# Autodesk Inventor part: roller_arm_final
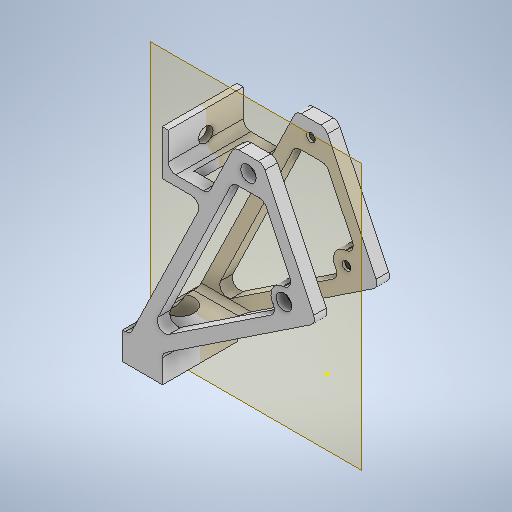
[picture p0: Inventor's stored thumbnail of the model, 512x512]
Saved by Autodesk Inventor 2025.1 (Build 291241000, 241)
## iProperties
Created: 2024-11
Part Number: roller_arm_final
Material: Generic
Document SubType Name: Modeling
Designer: mansa
Density: 1 g/cm^3
Appearance: Default
Author: mansa
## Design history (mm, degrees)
sketch "Sketch1"
  geometry: 1 further point
feature "Surface1"
workplane "Work Plane1"
sketch "Sketch2"
  geometry: L1 (16, 0)-(0, 0) reference; L2 (16, 0)-(16, 11) reference; L3 (16, 11)-(0, 11) reference; L4 (0, 0)-(0, 11) reference; 1 further point
extrude "Extrusion1" new body sketch "Sketch2" stored distance "d0" = 20; taper "d1" = 0 deg
sketch "Sketch6"
  geometry: L1 (16, 0)-(6, 0); L2 (6, 0)-(6, -20); L3 (6, -20)-(16, -20); L4 (16, -20)-(16, 0); L5 (16, 0)-(16, -20) reference; L6 (0, 0)-(16, 0) reference; 2 further points
  constraints: 8 end point, 2 parallel, 1 horizontal, 1 midpoint, 1 perpendicular
  dimensions: "d7" = 20 distance between parallel lines of L3 L1; "d8" = 10 distance of L1.start L1.end; "d10" = 0 distance between parallel lines of L5 L4; "d11" = 0 distance from line of point (8, 0) L1
sketch "Sketch8"
  geometry: L1 (56, 44.1)-(46, 44.1); L2 (46, 44.1)-(46, 24.1); L3 (46, 24.1)-(56, 24.1); L4 (56, 24.1)-(56, 44.1); L5 (16.187, 44.1)-(6.187, 44.1) reference; L6 (6.187, 24.1)-(16.187, 24.1) reference; 3 further points; 1 other entity
  constraints: 8 end point, 2 parallel, 1 collinear, 1 horizontal, 1 perpendicular, 1 other
  dimensions: "d13" = 10 distance between parallel lines of L2 L4; "d14" = 20 distance of L3.end L1.start; "d15" = 30 dimension on L2
loft "Loft1" sketch "Sketch6", "Sketch8" dims "d16" = 0, "d17" = 90 deg, "d18" = 0, "d19" = 90 deg
sketch "Sketch9"
  geometry: L1 (48.4, 69.2)-(116.6, 69.2) reference; L2 (72.5, 69.2)-(92.5, 69.2); L3 (92.5, 69.2)-(92.5, 87.2); L4 (92.5, 87.2)-(72.5, 87.2); L5 (72.5, 87.2)-(72.5, 69.2); L6 (48.4, 91)-(116.6, 91) reference; L7 (82.5, 91)-(82.5, 65.399); 1 further point
  constraints: 10 end point, 2 parallel, 2 perpendicular, 1 horizontal, 1 midpoint, 1 point on line, 1 other
  dimensions: "d20" = 18 distance of L4.end L2.start; "d21" = 20 distance of L3.end L4.end
extrude "Extrusion2" join sketch "Sketch9" distance "d22" = 2.5; taper "d23" = 0 deg
sketch "Sketch10"
  geometry: L1 (72.5, 87.2)-(72.5, 69.2) reference; L2 (72.5, 69.2)-(92.5, 69.2) reference; L3 (72.5, 73.2)-(92.5, 73.2); L4 (92.5, 73.2)-(92.5, 69.2); L5 (92.5, 69.2)-(72.5, 69.2); L6 (72.5, 69.2)-(72.5, 73.2); 1 further point
  constraints: 8 end point, 2 parallel, 1 horizontal, 1 perpendicular, 1 point on line
  dimensions: "d24" = 4 distance of L3.end L2.end
extrude "Extrusion3" join sketch "Sketch10" stored distance "d25" = 2.5; taper "d26" = 0 deg
feature "Surface2"
feature "Surface3"
sketch "Sketch13"
  geometry: L1 (39.813, 84.757)-(0, 11) reference; L2 (39.813, 84.757)-(55.958, 51.122); L3 (55.958, 51.122)-(0, 11); 1 further point
  constraints: 4 end point
  dimensions: "d33" = 26 deg angle of L3 L1; "d34" = 54 deg angle of L1 L2
extrude "Extrusion5" join sketch "Sketch13" stored distance "d35" = 20; taper "d36" = 0 deg
fillet "Fillet2" dims "d37" = 3
sketch "Sketch14"
  geometry: C1 r 2.75 at (34.813, 78.792) reference; C2 r 2.75 at (48.6, 53.017) reference; C3 r 1.75 at (34.813, 78.792); C4 r 1.75 at (48.6, 53.017); 1 further point
  constraints: 2 centre point, 2 coincident
  dimensions: "d39" = 3.5 diameter of C3; "d40" = 3.5 diameter of C4 (= d39)
extrude "Extrusion6" cut sketch "Sketch14" extent not by distance; stored distance "d41" = 10; taper "d42" = 0 deg
workplane "Work Plane5"
sketch "Sketch15"
  geometry: L1 (92.5, 87.2)-(72.5, 87.2) reference; L2 (72.5, 51.234)-(72.5, 80.898) reference; L3 (92.5, 51.234)-(92.5, 80.898) reference; L4 (72.5, 9.74)-(72.5, 47.498) reference; L5 (92.5, 9.74)-(92.5, 47.498) reference; L6 (92.5, 9.74)-(72.5, 9.74) reference; L7 (72.5, 87.2)-(72.5, 76.2) reference; L8 (92.5, 76.2)-(92.5, 87.2) reference; L9 (77.5, 85.2)-(87.5, 85.2); L10 (87.5, 85.2)-(87.5, 12.2); L11 (87.5, 12.2)-(77.5, 12.2); L12 (77.5, 12.2)-(77.5, 85.2); 2 further points
  constraints: 8 end point, 2 parallel, 1 horizontal, 1 midpoint, 1 perpendicular
  dimensions: "d45" = 5 distance between parallel lines of L2 L12; "d46" = 5 distance between parallel lines of L3 L10; "d48" = 73 distance between parallel lines of L11 L9; "d49" = 2 distance from line of point (82.5, 85.2) L1
extrude "Extrusion7" cut sketch "Sketch15" distance "d50" = 63.75; taper "d51" = 0 deg
sketch "Sketch16"
  geometry: L1 (77.5, 39.064)-(87.5, 39.064) reference; L2 (77.5, 13.369)-(77.5, 39.064) reference; L3 (87.5, 13.369)-(77.5, 13.369) reference; L4 (87.5, 39.064)-(87.5, 13.369) reference; 1 further point
extrude "Extrusion8" cut sketch "Sketch16" distance "d52" = 34; taper "d53" = 0 deg
sketch "Sketch17"
  geometry: L1 (-1.252, 11.898)-(-53.912, 49.655); L2 (-20.191, 66.932)-(9.15, 12.575); L3 (-28.963, 83.182)-(-25.589, 76.932); L4 (-37.925, 84.757)-(-31.603, 84.757); L5 (-54.868, 53.391)-(-40.63, 83.055); L6 (-32.433, 72.4)-(-43.132, 50.112); L7 (-42.494, 47.621)-(-5.414, 21.034); L8 (-2.488, 23.609)-(-28.87, 72.485); A1 r 3 centre (-52.164, 52.093) between (-54.868, 53.391) and (-53.912, 49.655); A2 r 3 centre (-31.603, 81.757) between (-28.963, 83.182) and (-31.603, 84.757); A3 r 3 centre (-37.925, 81.757) between (-37.925, 84.757) and (-40.63, 83.055); A4 r 2 centre (-4.248, 22.659) between (-5.414, 21.034) and (-2.488, 23.609); A5 r 2 centre (-30.63, 71.535) between (-28.87, 72.485) and (-32.433, 72.4); A6 r 2 centre (-41.329, 49.246) between (-43.132, 50.112) and (-42.494, 47.621); 1 further point
  constraints: 6 centre point, 6 end point, 6 point on circle, 6 tangent, 3 parallel, 2 equal radius
  dimensions: "d54" = 5 distance between parallel lines of L2 L8; "d55" = 5 distance between parallel lines of L1 L7; "d56" = 12 distance between parallel lines of L5 L6; "d57" = 2 radius of A4 (derived)
extrude "Extrusion9" cut sketch "Sketch17" extent not by distance; stored distance "d58" = 0; taper "d59" = 0 deg
sketch "Sketch18"
  geometry: L1 (92.5, 87.2)-(72.5, 87.2) reference; L2 (82.5, 87.2)-(82.5, 73.2); L3 (72.5, 73.2)-(92.5, 73.2) reference; C1 r 2.9 at (82.5, 80.1); 1 further point
  constraints: 2 end point, 2 midpoint, 1 centre point, 1 point on line
  dimensions: "d61" = 7.1 distance from line of C1.centre L1; "d62" = 5.8 diameter of C1
extrude "Hole top" cut sketch "Sketch18" extent not by distance; stored distance "d63" = 0; taper "d64" = 0 deg
workplane "Work Plane6"
sketch "Sketch20"
  geometry: L1 (0, 20)-(0, 0) reference; L2 (16, 20)-(16, 0) reference; L3 (0, 0)-(16, 20); L4 (0, 20)-(16, 0); C1 r 2.9 at (8, 10); 1 further point
  constraints: 4 end point, 1 centre point, 1 midpoint
  dimensions: "d68" = 5.8 diameter of C1
extrude "hole bottom 2" cut sketch "Sketch20" distance "d69" = 4; taper "d70" = 0 deg
sketch "Sketch21"
  geometry: C1 r 5.5 at (0, 0); 1 further point
  constraints: 1 centre point
  dimensions: "d71" = 11 diameter of C1
extrude "Hole bottom" cut sketch "Sketch21" extent not by distance; stored distance "d72" = 0; taper "d73" = 0 deg
workplane "Work Plane7"
split "Split1"
sketch "Sketch22"
  geometry: C1 r 1.75 at (48.787, -18.34) reference; C2 r 1.75 at (35, 7.435) reference; C3 r 3.1 at (35, 7.435); C4 r 3.1 at (48.787, -18.34); 1 further point
  constraints: 2 centre point, 2 coincident
  dimensions: "d78" = 6.2 diameter of C4; "d79" = 6.2 diameter of C3 (= d78)
extrude "Extrusion14" cut sketch "Sketch22" distance "d80" = 4; taper "d81" = 0 deg
node "Direct Edit2"
sketch "Sketch23"
  geometry: L1 (-37.382, 8.81)-(-36.588, 10.185) reference; L2 (-38.175, 7.435)-(-37.382, 8.81) reference; L3 (-37.382, 6.06)-(-38.175, 7.435) reference; L4 (-36.588, 4.685)-(-37.382, 6.06) reference; L5 (-35, 4.685)-(-36.588, 4.685) reference; L6 (-33.412, 4.685)-(-35, 4.685) reference; L7 (-33.412, 4.685)-(-32.618, 6.06) reference; L8 (-32.618, 6.06)-(-31.825, 7.435) reference; L9 (-31.825, 7.435)-(-32.618, 8.81) reference; L10 (-32.618, 8.81)-(-33.412, 10.185) reference; L11 (-33.412, 10.185)-(-35, 10.185) reference; L12 (-35, 10.185)-(-36.588, 10.185) reference; L13 (-36.876, 10.685)-(-37.815, 9.06); L14 (-37.815, 9.06)-(-38.753, 7.435); L15 (-38.753, 7.435)-(-37.815, 5.81); L16 (-37.815, 5.81)-(-36.876, 4.185); L17 (-36.876, 4.185)-(-35, 4.185); L18 (-35, 4.185)-(-33.124, 4.185); L19 (-33.124, 4.185)-(-32.185, 5.81); L20 (-32.185, 5.81)-(-31.247, 7.435); L21 (-31.247, 7.435)-(-32.185, 9.06); L22 (-32.185, 9.06)-(-33.124, 10.685); L23 (-33.124, 10.685)-(-35, 10.685); L24 (-35, 10.685)-(-36.876, 10.685); L25 (-50.375, -15.59)-(-51.168, -16.965) reference; L26 (-51.168, -16.965)-(-51.962, -18.34) reference; L27 (-48.787, -15.59)-(-50.375, -15.59) reference; L28 (-47.199, -15.59)-(-48.787, -15.59) reference; L29 (-46.405, -16.965)-(-47.199, -15.59) reference; L30 (-45.611, -18.34)-(-46.405, -16.965) reference; L31 (-46.405, -19.715)-(-45.611, -18.34) reference; L32 (-47.199, -21.09)-(-46.405, -19.715) reference; L33 (-48.787, -21.09)-(-47.199, -21.09) reference; L34 (-50.375, -21.09)-(-48.787, -21.09) reference; L35 (-51.168, -19.715)-(-50.375, -21.09) reference; L36 (-51.962, -18.34)-(-51.168, -19.715) reference; L37 (-46.91, -15.09)-(-48.787, -15.09); L38 (-48.787, -15.09)-(-50.663, -15.09); L39 (-50.663, -15.09)-(-51.601, -16.715); L40 (-51.601, -16.715)-(-52.54, -18.34); L41 (-52.54, -18.34)-(-51.601, -19.965); L42 (-51.601, -19.965)-(-50.663, -21.59); L43 (-50.663, -21.59)-(-48.787, -21.59); L44 (-48.787, -21.59)-(-46.91, -21.59); L45 (-46.91, -21.59)-(-45.972, -19.965); L46 (-45.972, -19.965)-(-45.034, -18.34); L47 (-45.034, -18.34)-(-45.972, -16.715); L48 (-45.972, -16.715)-(-46.91, -15.09); 1 further point
  constraints: 48 end point, 22 other
  dimensions: "d88" = 0.5 distance between parallel lines of L12 L24; "d89" = 0.5 distance between parallel lines of L29 L48 (= d88)
extrude "Extrusion15" cut sketch "Sketch23" distance "d90" = 4; taper "d91" = 0 deg
fillet "Fillet5" dims "d92" = 2
workplane "Work Plane8"
feature "Surface4"
sketch "Sketch24"
  geometry: L1 (0, 18)-(2.5, 18) reference; L2 (2.5, 18)-(2.5, 7) reference; L3 (0, 18)-(0, 0) reference; L4 (0, 0)-(11.723, 0); L5 (5.5, 4)-(16.577, 4); L6 (-15.813, -60.357)-(0.187, -60.357) reference; L7 (-15.813, -71.357)-(-15.813, -60.357) reference; L8 (0.187, -71.357)-(0.187, -60.357) reference; L9 (-15.813, -71.357)-(0.187, -71.357) reference; L10 (34.554, 5.273)-(34.554, -8.091); L11 (0, 0)-(0, 18); L12 (2.5, 18)-(2.5, 7); L13 (2.5, 7)-(2.5, 18); L14 (2.5, 18)-(0, 18); L15 (0, 18)-(0, 0); L16 (-14.658, -60.357)-(-15.813, -60.357); L17 (-15.813, -71.357)-(-15.813, -60.357); L18 (-15.813, -71.357)-(0.187, -71.357); L19 (0.187, -71.357)-(0.187, -61.965); L20 (48.787, -18.34)-(80.365, -18.34); L21 (1.439, -59.46)-(54.099, -21.702) reference; L22 (30.644, 25.243)-(38.456, 25.243); L23 (41.16, 23.541)-(60.64, -17.042); L24 (55.055, -17.966)-(40.817, 11.698) reference; L25 (31.79, 13.4)-(38.112, 13.4) reference; L26 (20.378, -4.425)-(-8.963, -58.782) reference; L27 (27.945, 23.553)-(19.276, 5.69); L28 (14.422, -4.31)-(-11.959, -58.667); L29 (1.526, -59.467)-(59.597, -20.838); C1 r 4 at (34.554, 18.993) reference; C2 r 1.75 at (34.554, 18.993); C3 r 1.75 at (48.787, -18.34) reference; C4 r 1.75 at (48.787, -18.34); C5 r 1.75 at (48.787, -18.34); A1 r 3 centre (5.5, 7) between (2.5, 7) and (5.5, 4); A2 r 3 centre (3.187, -61.965) between (1.526, -59.467) and (0.187, -61.965); A3 r 3 centre (-14.658, -57.357) between (-14.658, -60.357) and (-11.959, -58.667); A4 r 3 centre (57.935, -18.34) between (59.597, -20.838) and (60.64, -17.042); A5 r 3 centre (30.644, 22.243) between (30.644, 25.243) and (27.945, 23.553); A6 r 3 centre (38.456, 22.243) between (41.16, 23.541) and (38.456, 25.243); A7 r 3 centre (16.577, 7) between (16.577, 4) and (19.276, 5.69); A8 r 3 centre (11.723, -3) between (14.422, -4.31) and (11.723, 0); 7 further points
  constraints: 36 end point, 16 point on circle, 16 tangent, 11 centre point, 11 point on line, 7 collinear, 5 horizontal, 4 equal radius, 3 coincident, 2 parallel, 2 vertical, 1 perpendicular, 1 symmetric about line
  dimensions: "d93" = 3 radius of A1; "d98" = 13 distance of point (11.021, 5.273) point (24.021, 5.273); "d102" = 3.5 diameter of C2; "d105" = 3 radius of A2; "d106" = 3 radius of A3 (derived); "d107" = 3 radius of A4 (derived); "d108" = 3 radius of A5 (derived); "d109" = 3 radius of A8 (derived); "d110" = 97.991 deg angle of L29 L23; "d111" = 64.1109 deg angle of L6 L28; "d112" = 7.81196 distance of L22.start L22.end
extrude "Extrusion16" new body sketch "Sketch24" stored distance "d113" = 21; taper "d114" = 0 deg
sketch "Sketch26"
  geometry: L1 (-1.642, -48.861)-(27.436, 11.053); L2 (30.135, 12.743)-(38.91, 12.743); L3 (41.614, 11.041)-(51.134, -8.792); L4 (48.429, -13.09)-(48.787, -13.09); L5 (2.718, -52.668)-(43.617, -25.463); L6 (1.526, -59.467)-(59.597, -20.838) reference; L7 (14.422, -4.31)-(-11.959, -58.667) reference; L8 (60.64, -17.042)-(41.16, 23.541) reference; L9 (38.456, 25.243)-(30.644, 25.243) reference; C1 r 1.75 at (48.787, -18.34) reference; A1 r 5.25 centre (48.787, -18.34) between (48.787, -13.09) and (44.439, -21.283); A2 r 3 centre (1.057, -50.17) between (-1.642, -48.861) and (2.718, -52.668); A3 r 3 centre (30.135, 9.743) between (30.135, 12.743) and (27.436, 11.053); A4 r 3 centre (38.91, 9.743) between (41.614, 11.041) and (38.91, 12.743); A5 r 3 centre (48.429, -10.09) between (48.429, -13.09) and (51.134, -8.792); A6 r 3 centre (41.955, -22.965) between (43.617, -25.463) and (44.439, -21.283); 2 further points
  constraints: 13 point on circle, 11 tangent, 10 end point, 6 centre point, 4 equal radius, 4 parallel, 2 horizontal, 1 concentric, 1 point on line
  dimensions: "d116" = 3 radius of A2 (derived); "d117" = 5 distance between parallel lines of L7 L1; "d118" = 5 distance between parallel lines of L6 L5; "d119" = 5 distance between parallel lines of L8 L3; "d120" = 12.5 distance between parallel lines of L9 L2; "d121" = 3.5 radial gap between concentric circles of A1 C1
extrude "Extrusion17" cut sketch "Sketch26" distance "d122" = 42.5; taper "d123" = 0 deg
workplane "Work Plane9"
sketch "Sketch27"
  geometry: L1 (5, 20.23)-(25, 20.23); L2 (25, 20.23)-(25, -64.467); L3 (25, -64.467)-(5, -64.467); L4 (5, -64.467)-(5, 20.23); L5 (30, -24.042)-(30, 16.541) reference; L6 (0, -24.042)-(0, 16.541) reference; L7 (0, 18.243)-(30, 18.243) reference; L8 (0, -66.467)-(30, -66.467) reference; 3 further points
  constraints: 8 end point, 2 parallel, 1 horizontal, 1 perpendicular
  dimensions: "d125" = 5 distance between parallel lines of L5 L2; "d126" = 5 distance between parallel lines of L6 L4 (derived); "d127" = 1.98739 distance between parallel lines of L7 L1; "d128" = 2 distance between parallel lines of L8 L3
extrude "Extrusion18" cut sketch "Sketch27" distance "d129" = 88; taper "d130" = 0 deg
sketch "Sketch28"
  geometry: L1 (5, -25.058)-(25, -25.058) reference; L2 (5, -36.509)-(5, -25.058) reference; L3 (5, -62.326)-(5, -27.838) reference; L4 (25, -27.838)-(25, -62.326) reference; L5 (25, -62.326)-(5, -62.326) reference; L6 (25, -25.058)-(25, -36.509) reference; 1 further point
extrude "Extrusion19" cut sketch "Sketch28" distance "d131" = 39.5; taper "d132" = 0 deg
sketch "Sketch29"
  geometry: L1 (0, -30)-(16, -30) reference; L2 (16, 0)-(16, -30) reference; L3 (0, 0)-(16, 0) reference; L4 (0, 0)-(0, -30) reference; L5 (8, 0)-(8, -30); L6 (0, -15)-(16, -15); C1 r 2.9 at (8, -15); 1 further point
  constraints: 5 midpoint, 4 end point, 1 centre point
  dimensions: "d133" = 5.8 diameter of C1
extrude "Extrusion20" cut sketch "Sketch29" extent not by distance; stored distance "d134" = 39.5; taper "d135" = 0 deg
sketch "Sketch30"
  geometry: C1 r 5.5 at (2.525, 10); A1 r 2.9 centre (2.525, 10) between (0, 8.574) and (0, 11.426) reference; A2 r 2.9 centre (2.525, 10) between (0, 11.426) and (0, 8.574) reference; 1 further point
  constraints: 1 centre point, 1 coincident
  dimensions: "d136" = 11 diameter of C1
extrude "Extrusion21" cut sketch "Sketch30" distance "d137" = 12.031; taper "d138" = 0 deg
sketch "Sketch31"
  geometry: L1 (-30, 18)-(-30, 0) reference; L2 (0, 0)-(-30, 0) reference; L3 (0, 18)-(0, 0) reference; L4 (0, 18)-(-30, 18) reference; L5 (-30, 9)-(0, 9); L6 (-15, 18)-(-15, 0); C1 r 2.9 at (-15, 9); 1 further point
  constraints: 5 midpoint, 4 end point, 1 centre point
  dimensions: "d139" = 5.8 diameter of C1
extrude "Extrusion22" cut sketch "Sketch31" distance "d140" = 12.031; taper "d141" = 0 deg
sketch "Sketch32"
  geometry: C1 r 1.75 at (34.554, 18.993) reference; C2 r 1.75 at (48.787, -18.34) reference; C3 r 3.1 at (34.554, 18.993); C4 r 3.1 at (48.787, -18.34); 1 further point
  constraints: 2 centre point, 2 coincident
  dimensions: "d143" = 6.2 diameter of C3; "d144" = 6.2 diameter of C4
extrude "Extrusion23" cut sketch "Sketch32" distance "d145" = 4; taper "d146" = 0 deg
sketch "Sketch33"
  geometry: L1 (-50.188, 55.767)-(-48.6, 55.767) reference; L2 (-48.6, 55.767)-(-47.012, 55.767) reference; L3 (-47.012, 55.767)-(-46.218, 54.392) reference; L4 (-46.218, 54.392)-(-45.424, 53.017) reference; L5 (-45.424, 53.017)-(-46.218, 51.642) reference; L6 (-46.218, 51.642)-(-47.012, 50.267) reference; L7 (-47.012, 50.267)-(-48.6, 50.267) reference; L8 (-48.6, 50.267)-(-50.188, 50.267) reference; L9 (-50.188, 50.267)-(-50.981, 51.642) reference; L10 (-50.981, 51.642)-(-51.775, 53.017) reference; L11 (-51.775, 53.017)-(-50.981, 54.392) reference; L12 (-50.981, 54.392)-(-50.188, 55.767) reference; L13 (-35.955, 93.1)-(-34.367, 93.1) reference; L14 (-34.367, 93.1)-(-32.78, 93.1) reference; L15 (-32.78, 93.1)-(-31.986, 91.725) reference; L16 (-31.986, 91.725)-(-31.192, 90.35) reference; L17 (-31.192, 90.35)-(-31.986, 88.975) reference; L18 (-31.986, 88.975)-(-32.78, 87.6) reference; L19 (-32.78, 87.6)-(-34.367, 87.6) reference; L20 (-34.367, 87.6)-(-35.955, 87.6) reference; L21 (-35.955, 87.6)-(-36.749, 88.975) reference; L22 (-36.749, 88.975)-(-37.543, 90.35) reference; L23 (-37.543, 90.35)-(-36.749, 91.725) reference; L24 (-36.749, 91.725)-(-35.955, 93.1) reference; L25 (-36.244, 93.6)-(-34.367, 93.6); L26 (-34.367, 93.6)-(-32.491, 93.6); L27 (-32.491, 93.6)-(-31.553, 91.975); L28 (-31.553, 91.975)-(-30.615, 90.35); L29 (-30.615, 90.35)-(-31.553, 88.725); L30 (-31.553, 88.725)-(-32.491, 87.1); L31 (-32.491, 87.1)-(-34.367, 87.1); L32 (-34.367, 87.1)-(-36.244, 87.1); L33 (-36.244, 87.1)-(-37.182, 88.725); L34 (-37.182, 88.725)-(-38.12, 90.35); L35 (-38.12, 90.35)-(-37.182, 91.975); L36 (-37.182, 91.975)-(-36.244, 93.6); L37 (-48.6, 56.267)-(-50.476, 56.267); L38 (-50.476, 56.267)-(-51.414, 54.642); L39 (-51.414, 54.642)-(-52.353, 53.017); L40 (-52.353, 53.017)-(-51.414, 51.392); L41 (-51.414, 51.392)-(-50.476, 49.767); L42 (-50.476, 49.767)-(-48.6, 49.767); L43 (-48.6, 49.767)-(-46.723, 49.767); L44 (-46.723, 49.767)-(-45.785, 51.392); L45 (-45.785, 51.392)-(-44.847, 53.017); L46 (-44.847, 53.017)-(-45.785, 54.642); L47 (-45.785, 54.642)-(-46.723, 56.267); L48 (-46.723, 56.267)-(-48.6, 56.267); 1 further point
  constraints: 48 end point, 22 other
  dimensions: "d147" = 0.5 distance between parallel lines of L14 L26; "d148" = 0.5 distance between parallel lines of L48 L2
extrude "Extrusion24" cut sketch "Sketch33" distance "d149" = 4; taper "d150" = 0 deg
fillet "Fillet6" dims "d151" = 2
workplane "Work Plane10"
body "Solid1"
node "Reference1"
node "Projected Loop1"
node "Reference2"
node "Reference3"
node "Reference4"
node "Reference5"
node "Reference6"
node "Reference7"
node "Reference8"
node "Reference9"
node "Reference10"
node "Reference11"
node "Reference12"
node "Reference13"
node "Reference14"
node "Reference15"
node "Reference16"
node "Reference17"
node "Reference18"
node "Reference19"
node "Reference20"
node "Reference21"
node "Reference22"
node "Reference23"
node "Reference24"
node "Reference25"
node "Reference26"
node "Reference27"
node "Reference28"
node "Reference29"
body "Solid2"
node "Projected Loop4"
node "Projected Loop5"
node "Reference30"
node "Reference31"
node "Reference32"
node "Reference33"
node "Reference34"
node "Reference35"
node "Reference36"
node "Reference37"
node "Reference38"
node "Reference39"
node "Reference40"
node "Reference41"
node "Reference42"
node "Reference43"
node "Reference44"
node "Reference45"
node "Reference46"
node "Reference47"
node "Reference48"
node "Reference49"
node "Reference50"
node "Reference51"
node "Reference52"
node "Reference53"
body "Srf1"
body "Srf2"
body "Srf3"
move_body "Move2" dims "d84" = 5
move_body "Move3" dims "d87" = 5
body "Srf4"
other parameters: "d44" = 67.75, "d82" = 0, "d83" = 0, "d85" = 0, "d86" = 0, "d124" = 93.25
